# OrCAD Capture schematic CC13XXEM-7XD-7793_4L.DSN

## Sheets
1 CC13xxEM-7XD-7793_4L: size A3; title: CC13xxEM-7XD-7793_4L, main; rev: 1.0.1
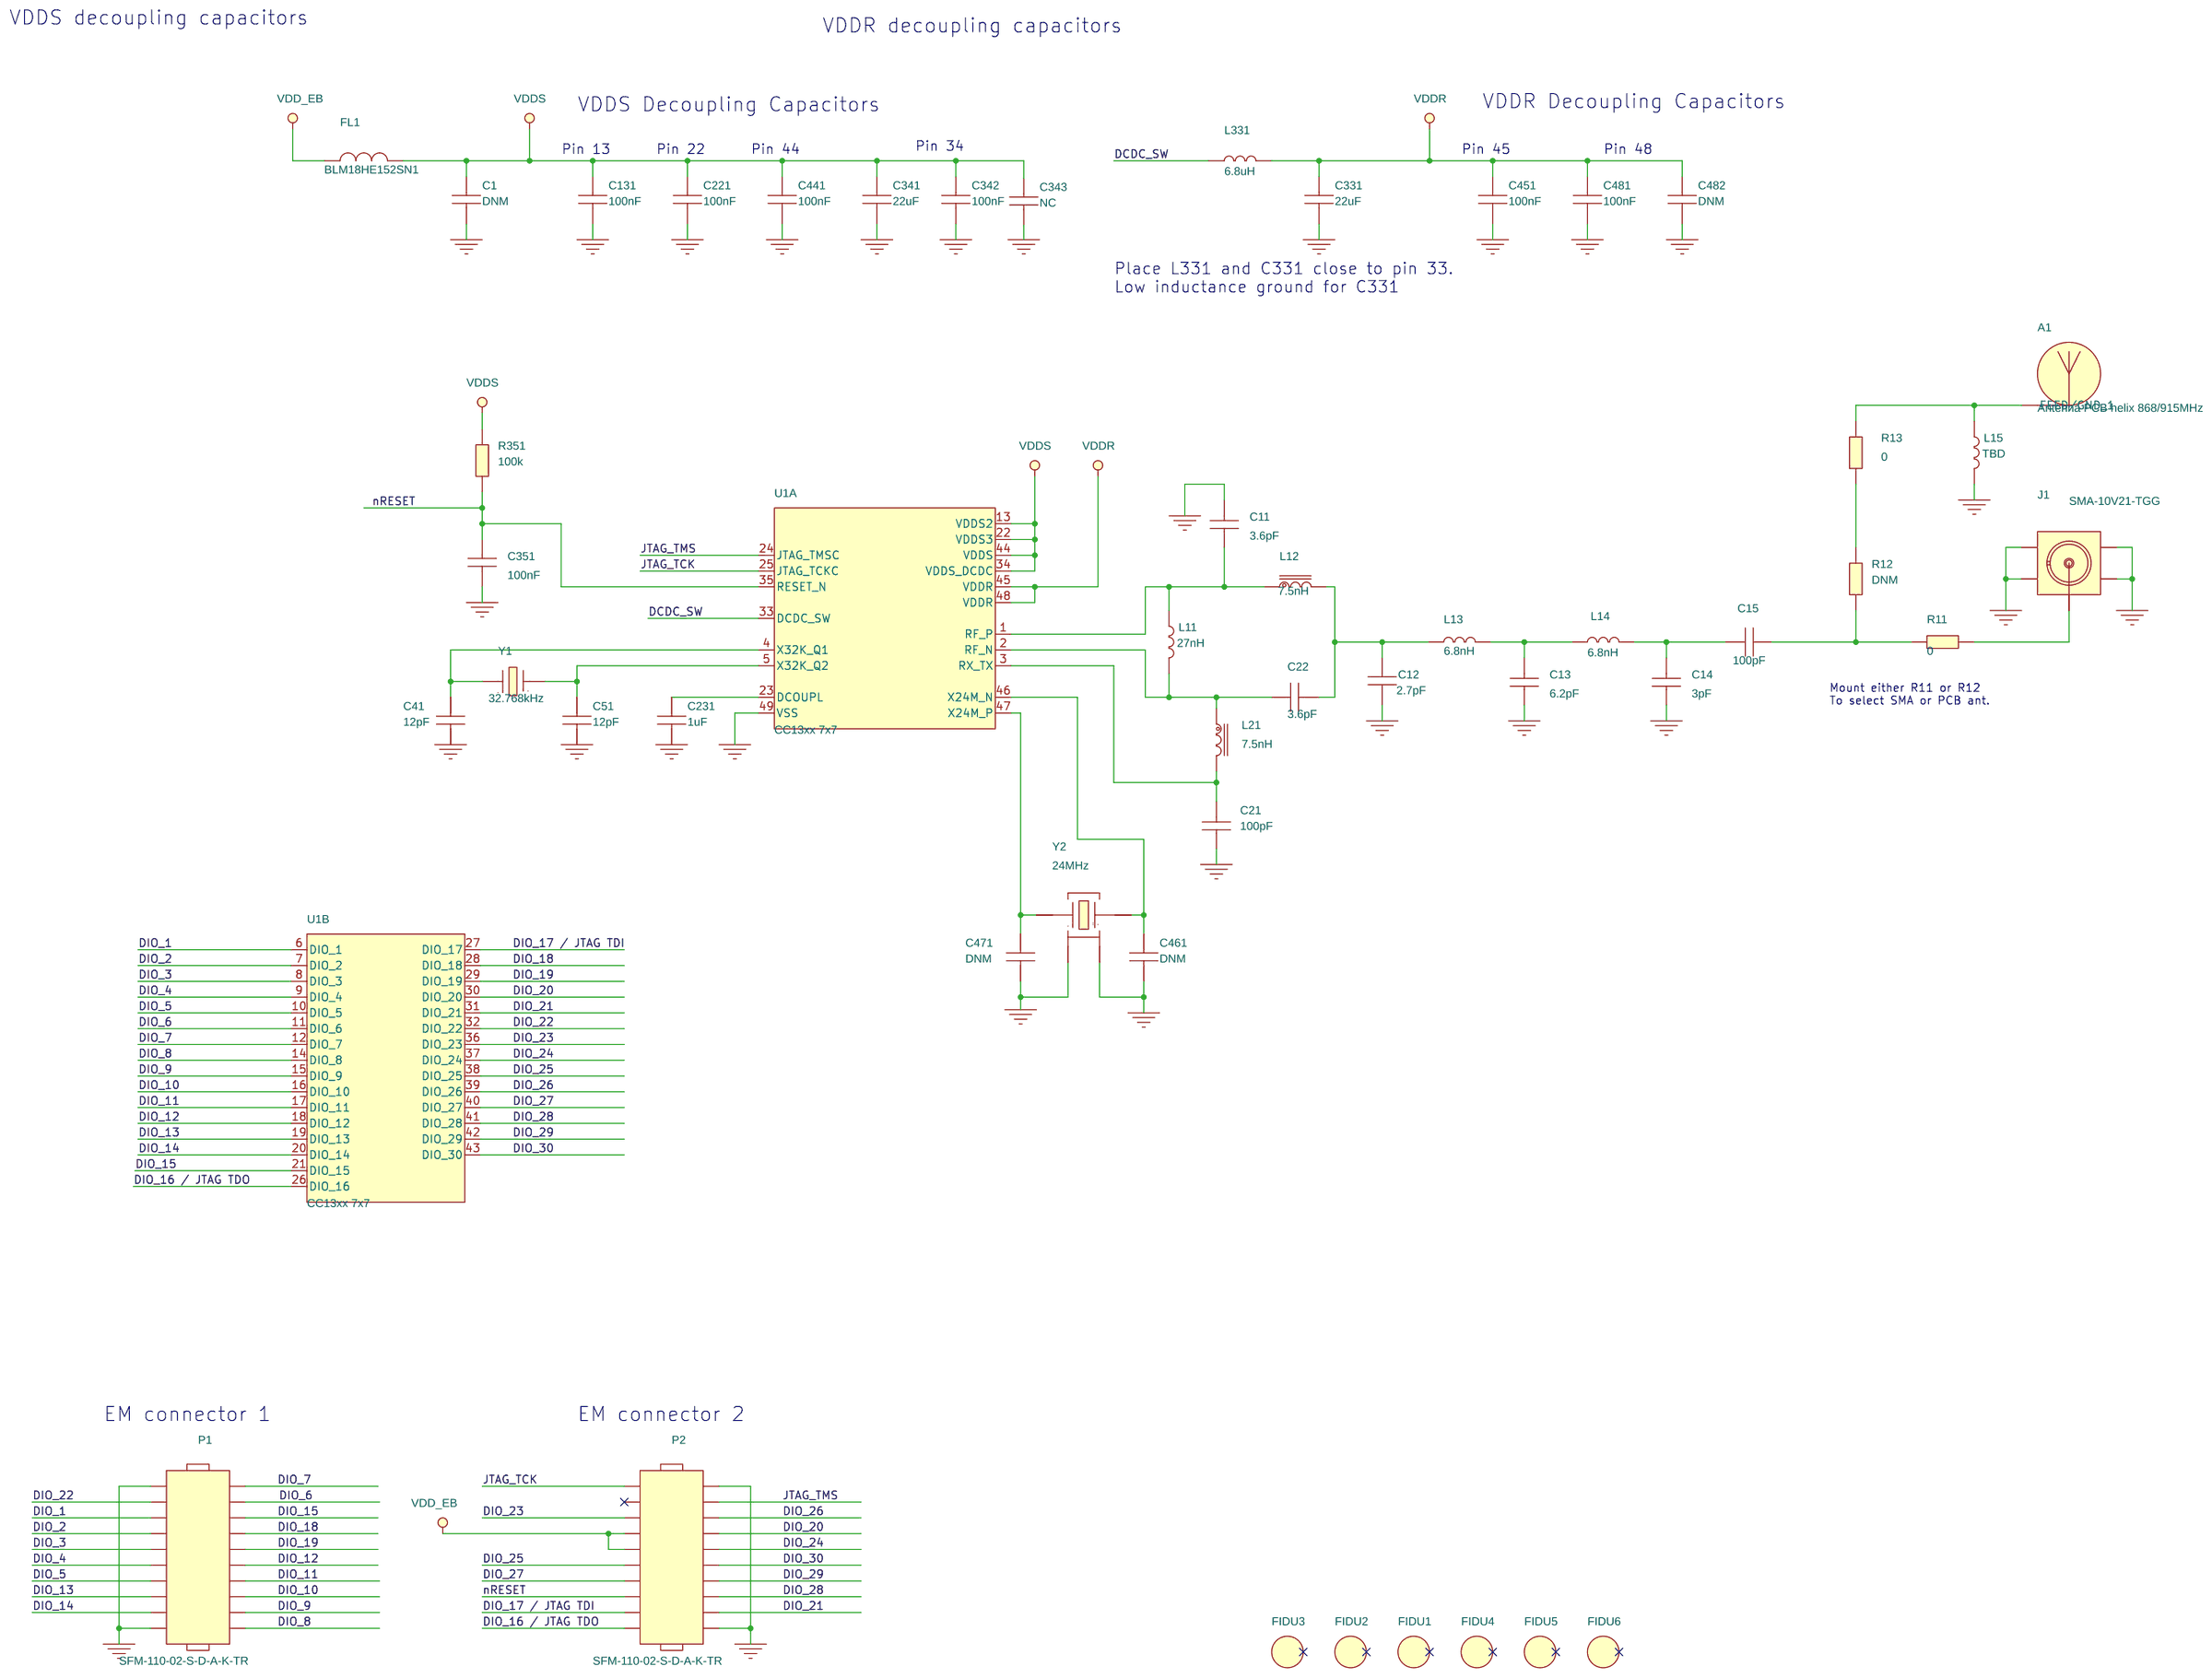
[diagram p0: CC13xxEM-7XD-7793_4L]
2 Revision: title: CC13xxEM-7XD-7793_4L, rev history
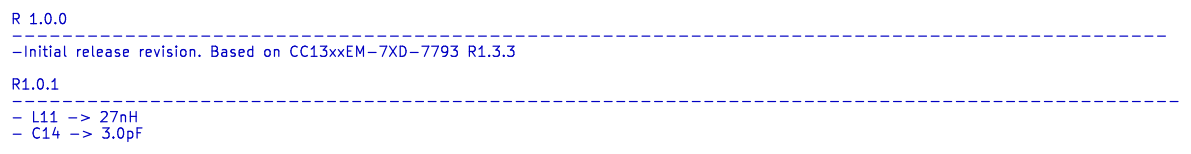
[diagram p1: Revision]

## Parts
A1  Antenna PCB helix 868/915MHz  [Antenna868_915MHz_A2N]
C1  DNM  [CAPC1608X90L]
C11  3.6pF  [CAPC1005X60L]
C12  2.7pF  [CAPC1005X60L]
C13  6.2pF  [CAPC1005X60L]
C14  3pF  [CAPC1005X60L]
C15  100pF  [CAPC1005X60L]
C21  100pF  [CAPC1005X60L]
C22  3.6pF  [CAPC1005X60L]
C41  12pF  [CAPC1005X60L]
C51  12pF  [CAPC1005X60L]
C131  100nF  [CAPC1005X60L]
C221  100nF  [CAPC1005X60L]
C231  1uF  [CAPC1005X60L]
C331  22uF  [CAPC1608X100A2L]
C341  22uF  [CAPC1608X100A2L]
C342  100nF  [CAPC1608X90L]
C343  NC  [CAPC1608X90L]
C351  100nF  [CAPC1005X60L]
C441  100nF  [CAPC1005X60L]
C451  100nF  [CAPC1005X60L]
C461  DNM  [CAPC1005X60L]
C471  DNM  [CAPC1005X60L]
C481  100nF  [CAPC1005X60L]
C482  DNM  [CAPC1005X60L]
FIDU1  FIDU_1MM  [FID100X115]
FIDU2  FIDU_1MM  [FID100X115]
FIDU3  FIDU_1MM  [FID100X115]
FIDU4  FIDU_1MM  [FID100X115]
FIDU5  FIDU_1MM  [FID100X115]
FIDU6  FIDU_1MM  [FID100X115]
FL1  BLM18HE152SN1  [FIL_BLM18HE152SN1DL]
J1  SMA-10V21-TGG  [HUSTSAN_SMA10V21TGGAN]
L11  27nH  [INDC1005X60L]
L12  7.5nH  [INDC1005X60A2L]
L13  6.8nH  [INDC1005X60L]
L14  6.8nH  [INDC1005X60L]
L15  TBD  [INDC1005X60L]
L21  7.5nH  [INDC1005X60A2L]
L331  6.8uH  [INDC2012X150L]
P1  SFM-110-02-S-D-A-K-TR  [SAMTEC_SFM11002AN]
P2  SFM-110-02-S-D-A-K-TR  [SAMTEC_SFM11002AN]
R11  0  [RESC1005X40L]
R12  DNM  [RESC1005X40L]
R13  0  [RESC1005X40L]
R351  100k  [RESC1005X40L]
U1  CC13xx 7x7  [QFNFC50P700X700X80-49CN]  (sections A,B)
Y1  32.768kHz  [XTAL_FC-135N]
Y2  24MHz  [OSCCC250X320X60-4L]

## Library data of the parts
A1 = ANTENNA: ANTENNA, NON COMPONENT, PCB HELIX 868/915MHz, NOT APPLY; AutoDoc File: http://notefied-dynamic-precision.com/DB/Apps/Desktop/Item/Object.aspx?id=87165; Budget Currency: N/A; Budget Price: N/A; Datasheet URL 1: N/A; Datasheet URL 2: www.ti.com; Definied Quality: COMMERCIAL; Esd Level: N/A; FPLIST: Antenna868_915MHz_A2N,Antenna868_915MHz_MIRROR_A2N,; Frequency: 868/915MHz; Last Time Buy: N/A; Lead Time: N/A; LifeCycle Status: ACTIVE; MPN: ANTENNA PCB HELIX 868/915MHz; MPN Status: ACTIVE; MSL: N/A; MTBF: N/A; MTBF Standard: N/A; Manufacturer: TEXAS INSTRUMENTS; Max Oper Temp: N/A; Min Oper Temp: N/A; Mounting Type: NOT APPLY; NOTE Status: PREFERRED; Old Footprint: Antenna868_915MHz_A2N,Antenna868_915MHz_MIRROR_A2N; Packing Size: 2500; Packing Type: TAPE_&_REEL; Part Number: 13-00397; Part Type: MECHANIC\ANTENNA\NON_COMPONENT; Revision: R003; RoHS Status: ROHS_COMPLIANT; WEIGHT: N/A
C1 = CAPACITOR: CAPACITOR, DO NOT MOUNT, 0603, SMD; ALT_SYMBOLS: CAPC1608X90L,CAPC1608X90M; AutoDoc File: http://notefied-dynamic-precision.com/DB/Apps/Desktop/Item/Object.aspx?id=50475; FPLIST: CAPC1608X90N,CAPC1608X90L,CAPC1608X90M; Old Footprint: CAPC1608X90N,0603; Part Number: 02-01324; Part Type: CAPACITOR\CERAMIC\0603; Revision: R003
C11 C22 = CAPACITOR: CAPACITOR, CERAMIC C0G/NP0, 3.6pF, 50V, -0.25pF/+0.25pF, -55DEGC/+125DEGC, 0402, SMD; ALT_SYMBOLS: CAPC1005X60L,CAPC1005X60M; AutoDoc File: http://notefied-dynamic-precision.com/DB/Apps/Desktop/Item/Object.aspx?id=95903; Datasheet URL 2: http://psearch.murata.com/capacitor/product/GRM1555C1H3R6CA01%23.pdf; Dielectric Type: C0G/NP0; FPLIST: CAPC1005X60N,CAPC1005X60L,CAPC1005X60M; MPN: GRM1555C1H3R6CA01D; MPN Status: ACTIVE; Manufacturer: MURATA; Max Oper Temp: +125DEGC; Max Tol: +0.25pF; Min Oper Temp: -55DEGC; Min Tol: -0.25pF; Mounting Type: SMD; NOTE Status: PREFERRED; Old Footprint: CAPC1005X60N; PCB Package: 0402; Packing Size: 10000; Packing Type: TAPE_&_REEL; Part Number: 02-06008; Part Type: CAPACITOR\CERAMIC\0402; Revision: R001; RoHS Status: ROHS_COMPLIANT; Rtd Voltage: 50V
C12 = CAPACITOR: CAPACITOR, CERAMIC C0G/NP0, 2.7pF, 50V, -0.25pF/+0.25pF, -55DEGC/+125DEGC, 0402, SMD; ALT_SYMBOLS: CAPC1005X60L,CAPC1005X60M; AutoDoc File: http://notefied-dynamic-precision.com/DB/Apps/Desktop/Item/Object.aspx?id=87809; Budget Currency: EUR; Budget Price: 0.006; Datasheet URL 1: http://search.murata.co.jp/Ceramy/image/img/w_hinm/L0005E.pdf; Datasheet URL 2: http://psearch.murata.com/capacitor/product/GRM1555C1H2R7CA01%23.pdf; Definied Quality: INDUSTRIAL; Dielectric Type: C0G/NP0; Esd Level: N/A; FPLIST: CAPC1005X60N,CAPC1005X60L,CAPC1005X60M; Last Time Buy: N/A; Lead Time: 12; MPN: GRM1555C1H2R7CA01D; MPN Status: ACTIVE; MSL: 1; MTBF: N/A; MTBF Standard: N/A; Manufacturer: MURATA; Max Oper Temp: +125DEGC; Max Tol: +0.25pF; Min Oper Temp: -55DEGC; Min Tol: -0.25pF; Mounting Type: SMD; NOTE Status: PREFERRED; Old Footprint: CAPC1005X60N; PCB Package: 0402; Packing Size: 10000; Packing Type: TAPE_&_REEL; Part Number: 02-04679; Part Type: CAPACITOR\CERAMIC\0402; Revision: R001; RoHS Status: ROHS_COMPLIANT; Rtd Voltage: 50V; WEIGHT: 0.0016g
C13 = CAPACITOR: CAPACITOR, CERAMIC C0G/NP0, 6.2pF, 50V, -0.25pF/+0.25pF, -55DEGC/+125DEGC, 0402, SMD; ALT_SYMBOLS: CAPC1005X60L,CAPC1005X60M; AutoDoc File: http://notefied-dynamic-precision.com/DB/Apps/Desktop/Item/Object.aspx?id=87255; Budget Currency: EUR; Budget Price: 0.006; Datasheet URL 1: http://search.murata.co.jp/Ceramy/image/img/w_hinm/L0005E.pdf; Datasheet URL 2: http://psearch.murata.com/capacitor/product/GRM1555C1H6R2CA01%23.pdf; Definied Quality: INDUSTRIAL; Dielectric Type: C0G/NP0; Esd Level: N/A; FPLIST: CAPC1005X60N,CAPC1005X60L,CAPC1005X60M; Last Time Buy: N/A; Lead Time: 10; MPN: GRM1555C1H6R2CA01D; MPN Status: ACTIVE; MSL: 1; MTBF: N/A; MTBF Standard: N/A; Manufacturer: MURATA; Max Oper Temp: +125DEGC; Max Tol: +0.25pF; Min Oper Temp: -55DEGC; Min Tol: -0.25pF; Mounting Type: SMD; NOTE Status: PREFERRED; Old Footprint: CAPC1005X60N; PCB Package: 0402; Packing Size: 10000; Packing Type: TAPE_&_REEL; Part Number: 02-04608; Part Type: CAPACITOR\CERAMIC\0402; Revision: R001; RoHS Status: ROHS_COMPLIANT; Rtd Voltage: 50V; WEIGHT: 0.0016g
C14 = CAPACITOR: CAPACITOR, CERAMIC C0G/NP0, 3pF, 50V, -0.25pF/+0.25pF, -55DEGC/+125DEGC, 0402, SMD; ALT_SYMBOLS: CAPC1005X60L,CAPC1005X60M; AutoDoc File: http://notefied-dynamic-precision.com/DB/Apps/Desktop/Item/Object.aspx?id=87252; Budget Currency: EUR; Budget Price: 0.006; Datasheet URL 1: http://search.murata.co.jp/Ceramy/image/img/w_hinm/L0005E.pdf; Datasheet URL 2: http://psearch.murata.com/capacitor/product/GRM1555C1H3R0CA01%23.pdf; Definied Quality: INDUSTRIAL; Dielectric Type: C0G/NP0; Esd Level: N/A; FPLIST: CAPC1005X60N,CAPC1005X60L,CAPC1005X60M; Last Time Buy: N/A; Lead Time: 16; LifeCycle Status: ACTIVE; MPN: GRM1555C1H3R0CA01D; MPN Status: ACTIVE; MSL: 1; MTBF: N/A; MTBF Standard: N/A; Manufacturer: MURATA; Max Oper Temp: +125DEGC; Max Tol: +0.25pF; Min Oper Temp: -55DEGC; Min Tol: -0.25pF; Mounting Type: SMD; NOTE Status: PREFERRED; Old Footprint: CAPC1005X60N; PCB Package: 0402; Packing Size: 10000; Packing Type: TAPE_&_REEL; Part Number: 02-04606; Part Type: CAPACITOR\CERAMIC\0402; Revision: R001; RoHS Status: ROHS_COMPLIANT; Rtd Voltage: 50V; WEIGHT: 0.0016g
C15 C21 = CAPACITOR: CAPACITOR, CERAMIC C0G/NP0, 100pF, 50V, -5%/+5%, -55DEGC/+125DEGC, 0402, SMD; ALT_SYMBOLS: CAPC1005X60L,CAPC1005X60M; AutoDoc File: http://notefied-dynamic-precision.com/DB/Apps/Desktop/Item/Object.aspx?id=86072; Budget Currency: EUR; Budget Price: 0.006; Datasheet URL 1: http://search.murata.co.jp/Ceramy/image/img/w_hinm/L0005E.pdf; Datasheet URL 2: http://psearch.murata.com/capacitor/product/GRM1555C1H101JA01%23.pdf; Definied Quality: INDUSTRIAL; Dielectric Type: C0G/NP0; Esd Level: N/A; FPLIST: CAPC1005X60N,CAPC1005X60L,CAPC1005X60M; Last Time Buy: N/A; Lead Time: 12; MPN: GRM1555C1H101JA01D; MPN Status: ACTIVE; MSL: 1; MTBF: N/A; MTBF Standard: N/A; Manufacturer: MURATA; Max Oper Temp: +125DEGC; Max TC: +30PPM/DEGC; Max Tol: +5%; Min Oper Temp: -55DEGC; Min TC: -30PPM/DEGC; Min Tol: -5%; Mounting Type: SMD; NOTE Status: PREFERRED; Old Footprint: CAPC1005X60N; PCB Package: 0402; Packing Size: 10000; Packing Type: TAPE_&_REEL; Part Number: 02-04365; Part Type: CAPACITOR\CERAMIC\0402; Revision: R002; RoHS Status: ROHS_COMPLIANT; Rtd Voltage: 50V; WEIGHT: 0.0016g
C41 C51 = CAPACITOR: CAPACITOR, CERAMIC C0G/NP0, 12pF, 50V, -5%/+5%, -55DEGC/+125DEGC, 0402, SMD; ALT_SYMBOLS: CAPC1005X60L,CAPC1005X60M; AutoDoc File: http://notefied-dynamic-precision.com/DB/Apps/Desktop/Item/Object.aspx?id=84867; Budget Currency: EUR; Budget Price: 0.006; Datasheet URL 1: http://search.murata.co.jp/Ceramy/image/img/w_hinm/L0005E.pdf; Datasheet URL 2: http://psearch.murata.com/capacitor/product/GRM1555C1H120JA01%23.pdf; Definied Quality: INDUSTRIAL; Dielectric Type: C0G/NP0; Esd Level: N/A; FPLIST: CAPC1005X60N,CAPC1005X60L,CAPC1005X60M; Last Time Buy: N/A; Lead Time: 12; MPN: GRM1555C1H120JA01D; MPN Status: ACTIVE; MSL: 1; MTBF: N/A; MTBF Standard: N/A; Manufacturer: MURATA; Max Oper Temp: +125DEGC; Max TC: +30PPM/DEGC; Max Tol: +5%; Min Oper Temp: -55DEGC; Min TC: -30PPM/DEGC; Min Tol: -5%; Mounting Type: SMD; NOTE Status: PREFERRED; Old Footprint: CAPC1005X60N; PCB Package: 0402; Packing Size: 10000; Packing Type: TAPE_&_REEL; Part Number: 02-04168; Part Type: CAPACITOR\CERAMIC\0402; Revision: R000; RoHS Status: ROHS_COMPLIANT; Rtd Voltage: 50V; WEIGHT: 0.0016g
C131 C221 C351 C441 C451 C481 = CAPACITOR: CAPACITOR, CERAMIC X7R, 100nF, 6.3V, -10%/+10%, -55DEGC/+125DEGC, 0402, SMD; ALT_SYMBOLS: CAPC1005X60L,CAPC1005X60M; AutoDoc File: http://notefied-dynamic-precision.com/DB/Apps/Desktop/Item/Object.aspx?id=73748; Budget Currency: EUR; Budget Price: 0.003; Datasheet URL 1: http://search.murata.co.jp/Ceramy/image/img/A01X/G101/ENG/GRM155R70J104KA01-01.pdf; Datasheet URL 2: http://search.murata.co.jp/Ceramy/image/img/A01X/G101/ENG/GRM155R70J104KA01-01.pdf; Dielectric Type: X7R; FPLIST: CAPC1005X60N,CAPC1005X60L,CAPC1005X60M; Lead Time: 10; LifeCycle Status: ACTIVE; MPN: GRM155R70J104KA01D; MPN Status: ACTIVE; Manufacturer: MURATA; Max Oper Temp: +125DEGC; Max Tol: +10%; Min Oper Temp: -55DEGC; Min Tol: -10%; Mounting Type: SMD; NOTE Status: PREFERRED; Old Footprint: CAPC1005X60N,0402; PCB Package: 0402; Packing Size: 10000; Packing Type: TAPE_&_REEL; Part Number: 02-02323; Part Type: CAPACITOR\CERAMIC\0402; Revision: R000; RoHS Status: ROHS_COMPLIANT; Rtd Voltage: 6.3V; WEIGHT: 0.0016g
C231 = CAPACITOR: CAPACITOR, CERAMIC X5R, 1uF, 10V, -10%/+10%, -55DEGC/+85DEGC, 0402, SMD; ALT_SYMBOLS: CAPC1005X60L,CAPC1005X60M; AutoDoc File: http://notefied-dynamic-precision.com/DB/Apps/Desktop/Item/Object.aspx?id=74236; Budget Currency: EUR; Budget Price: 0.015; Datasheet URL 1: http://search.murata.co.jp/Ceramy/image/img/w_hinm/L0005E.pdf; Datasheet URL 2: http://psearch.murata.com/capacitor/product/GRM155R61A105KE15%23.pdf; Definied Quality: INDUSTRIAL; Dielectric Type: X5R; Esd Level: N/A; FPLIST: CAPC1005X60N,CAPC1005X60L,CAPC1005X60M; Last Time Buy: N/A; Lead Time: 14; MPN: GRM155R61A105KE15D; MPN Status: ACTIVE; MSL: 1; MTBF: N/A; MTBF Standard: N/A; Manufacturer: MURATA; Max Oper Temp: +85DEGC; Max Tol: +10%; Min Oper Temp: -55DEGC; Min Tol: -10%; Mounting Type: SMD; NOTE Status: PREFERRED; Old Footprint: CAPC1005X60N,0402; PCB Package: 0402; Packing Size: 10000; Packing Type: TAPE_&_REEL; Part Number: 02-02381; Part Type: CAPACITOR\CERAMIC\0402; Revision: R002; RoHS Status: ROHS_COMPLIANT; Rtd Voltage: 10V; WEIGHT: 0.0016g
C331 C341 = CAPACITOR: CAPACITOR, CERAMIC, X5R, 22uF, 6.3V, -20%/+20%, -55DEGC/+85DEGC, 0603, SMD; ALT_SYMBOLS: CAPC1608X100A2L,CAPC1608X100A2M; AutoDoc File: http://notefied-dynamic-precision.com/DB/Apps/Desktop/Item/Object.aspx?id=104385; Budget Currency: USD; Budget Price: 0.045; Datasheet URL 1: N/A; Datasheet URL 2: http://psearch.en.murata.com/capacitor/product/GRM188R60J226MEA0%23.pdf; Definied Quality: INDUSTRIAL; Dielectric Type: X5R; Esd Level: N/A; FPLIST: CAPC1608X100A2N,CAPC1608X100A2L,CAPC1608X100A2M; Last Time Buy: N/A; Lead Time: 26; LifeCycle Status: ACTIVE; MPN: GRM188R60J226MEA0D; MPN Status: ACTIVE; Manufacturer: MURATA; Max Oper Temp: +85DEGC; Max Tol: +20%; Min Oper Temp: -55DEGC; Min Tol: -20%; Mounting Type: SMD; NOTE Status: PREFERRED; Old Footprint: CAPC1608X100A2N; PCB Package: 0603; Packing Size: 4000; Packing Type: TAPE_&_REEL; Part Number: 02-07053; Part Type: CAPACITOR\CERAMIC\0603; Revision: R001; RoHS Status: ROHS_COMPLIANT; Rtd Voltage: 6.3V; WEIGHT: 0.0091g
C342 = CAPACITOR: CAPACITOR, CERAMIC X7R, 100nF, 25V, -10%/+10%, -55DEGC/+125DEGC, 0603, SMD; ALT_SYMBOLS: CAPC1608X90L,CAPC1608X90M; AutoDoc File: http://notefied-dynamic-precision.com/DB/Apps/Desktop/Item/Object.aspx?id=72070; Budget Currency: EUR; Budget Price: 0.006; Cage Code: C0151; Datasheet URL 1: http://search.murata.co.jp/Ceramy/image/img/w_hinm/L0005E.pdf; Datasheet URL 2: http://psearch.murata.com/capacitor/product/GRM188R71E104KA01%23.pdf; Definied Quality: INDUSTRIAL; Dielectric Type: X7R; Esd Level: N/A; FPLIST: CAPC1608X90N,CAPC1608X90L,CAPC1608X90M; Last Time Buy: N/A; Lead Time: 10; MPN: GRM188R71E104KA01D; MPN Status: NRND; MSL: 1; MTBF: N/A; MTBF Standard: N/A; Manufacturer: MURATA; Max Oper Temp: +125DEGC; Max Tol: +10%; Min Oper Temp: -55DEGC; Min Tol: -10%; Mounting Type: SMD; NOTE Status: PREFERRED; Old Footprint: CAPC1608X90N,0603; PCB Package: 0603; Packing Size: 4000; Packing Type: TAPE_&_REEL; Part Number: 02-01992; Part Type: CAPACITOR\CERAMIC\0603; Revision: R001; RoHS Status: ROHS_COMPLIANT; Rtd Voltage: 25V; WEIGHT: 0.0063g
C343 = CAPACITOR: CAPACITOR, CERAMIC, N/A VALUE, -55DEGC/+125DEGC, 0603, SMD; ALT_SYMBOLS: CAPC1608X90L,CAPC1608X90M; AutoDoc File: http://notefied-dynamic-precision.com/DB/Apps/Desktop/Item/Object.aspx?id=50386; Budget Currency: USD; Budget Price: 0.00262; Datasheet URL 1: N/A; Datasheet URL 2: N/A; Definied Quality: INDUSTRIAL; Esd Level: N/A; FPLIST: CAPC1608X90N,CAPC1608X90L,CAPC1608X90M; Last Time Buy: N/A; Lead Time: N/A; MPN: CAPACITOR_0603_N/A_M; MPN Status: ACTIVE; MSL: N/A; MTBF: N/A; MTBF Standard: N/A; Manufacturer: MANUFACTURER SELECTION; Max Oper Temp: +125DEGC; Min Oper Temp: -55DEGC; Mounting Type: SMD; NOTE Status: PREFERRED; Old Footprint: CAPC1608X90N,0603; PCB Package: 0603; Packing Size: 5000; Packing Type: TAPE_&_REEL; Part Number: 02-01235; Part Type: CAPACITOR\CERAMIC\0603; Revision: R001; RoHS Status: ROHS_COMPLIANT; WEIGHT: 0.002g
C461 C471 C482 = CAPACITOR: CAPACITOR, CERAMIC, N/A VALUE, -55DEGC/+125DEGC, 0402, SMD; ALT_SYMBOLS: CAPC1005X60L,CAPC1005X60M; AutoDoc File: http://notefied-dynamic-precision.com/DB/Apps/Desktop/Item/Object.aspx?id=84862; Budget Currency: USD; Budget Price: 0.00589; FPLIST: CAPC1005X60N,CAPC1005X60L,CAPC1005X60M; MPN: CAPACITOR_0402_DNM_N/A_M; MPN Status: ACTIVE; Manufacturer: Manufacturer selection; Max Oper Temp: +125DEGC; Min Oper Temp: -55DEGC; Mounting Type: SMD; NOTE Status: PREFERRED; Old Footprint: CAPC1005X60N; PCB Package: 0402; Packing Size: 10000; Packing Type: TAPE_&_REEL; Part Number: 02-04164; Part Type: CAPACITOR\CERAMIC\0402; Revision: R000; RoHS Status: PART NOT KNOWN
FIDU1-FIDU6 = FIDMARK: FIDUCIAL MARK, ROUND 1MM; AutoDoc File: http://notefied-dynamic-precision.com/DB/Apps/Desktop/Item/Object.aspx?id=74548; Part Number: 19-00111; Part Type: NON_COMPONENT\FIDUCIAL; Revision: R001
FL1 = FILTER_2PIN: FILTER, EMI, 1500@100MHz, -55DEGC/+125DEGC, 0603, SMD; ALT_SYMBOLS: FIL_BLM18HE152SN1DL,FIL_BLM18HE152SN1DM; AutoDoc File: http://notefied-dynamic-precision.com/DB/Apps/Desktop/Item/Object.aspx?id=85575; Budget Currency: EUR; Budget Price: 0.085; Datasheet URL 1: http://search.murata.co.jp/Ceramy/image/img/PDF/ENG/L0110S0101BLM18H.pdf; Datasheet URL 2: http://search.murata.co.jp/Ceramy/image/img/PDF/ENG/L0110S0101BLM18H.pdf; FPLIST: FIL_BLM18HE152SN1DN,FIL_BLM18HE152SN1DL,FIL_BLM18HE152SN1DM; Impedance: 1500@100MHz; Lead Time: 26; MPN: BLM18HE152SN1D; MPN Status: ACTIVE; Manufacturer: MURATA; Max Oper Temp: +125DEGC; Max Tol: +25%; Min Oper Temp: -55DEGC; Min Tol: -25%; Mounting Type: SMD; NOTE Status: PREFERRED; Old Footprint: FIL_BLM18HE152SN1DN; PCB Package: 0603; Packing Size: 4000; Packing Type: TAPE_&_REEL; Part Number: 04-00470; Part Type: FILTER\EMI\0603; Revision: R001; RoHS Status: ROHS_COMPLIANT; Rtd Current: 0.5A; WEIGHT: 0.006g
J1 = CONN_COAX_1+4: CONNECTOR, COAX RF, STRAIGHT, FEMALE, 1 PIN, SMD; ALT_SYMBOLS: HUSTSAN_SMA10V21TGGL,HUSTSAN_SMA10V21TGGM; AutoDoc File: http://notefied-dynamic-precision.com/DB/Apps/Desktop/Item/Object.aspx?id=84956; Budget Currency: USD; Budget Price: 1.21; Datasheet URL 1: http://www.hustsan.com.tw/uploaddir/product/SMA-10V21.pdf; Datasheet URL 2: http://www.hustsan.com.tw/uploaddir/product/SMA-10V21.pdf; FPLIST: HUSTSAN_SMA10V21TGGAN,HUSTSAN_SMA10V21TGGN; Lead Time: 5; MPN Status: ACTIVE; MSL: N/A; Manufacturer: HUS-TSAN; Mounting Type: SMD; NOTE Status: PREFERRED; No Of Pos: 1; Old Footprint: HUSTSAN_SMA10V21TGGAN,HUSTSAN_SMA10V21TGGN; Packing Size: 350; Packing Type: TAPE_&_REEL; Part Number: 06-02188; Part Type: CONNECTOR\COAX; Revision: R003; RoHS Status: N/A; WEIGHT: N/A
L11 = INDUCTOR: INDUCTOR, STANDARD, CHIP, 27nH, -5%/+5%, 0.3A, -55DEGC/+125DEGC, 0402, SMD; ALT_SYMBOLS: INDC1005X60M,INDC1005X60L; AutoDoc File: http://notefied-dynamic-precision.com/DB/Apps/Desktop/Item/Object.aspx?id=85867; Budget Currency: EUR; Budget Price: 0.03; Datasheet URL 1: N/A; Datasheet URL 2: http://psearch.murata.com/inductor/product/LQG15HS27NJ02%23.pdf; Definied Quality: INDUSTRIAL; Esd Level: N/A; FPLIST: INDC1005X60N,INDC1005X60M,INDC1005X60L; Frequency: 1700MHz; Last Time Buy: N/A; Lead Time: 9; LifeCycle Status: ACTIVE; MPN: LQG15HS27NJ02D; MPN Status: ACTIVE; MSL: N/A; MTBF: N/A; MTBF Standard: N/A; Manufacturer: MURATA; Max Oper Temp: +125DEGC; Max Tol: +5%; Min Oper Temp: -55DEGC; Min Tol: -5%; Mounting Type: SMD; NOTE Status: PREFERRED; Old Footprint: INDC1005X60N; PCB Package: 0402; Packing Size: 10000; Packing Type: TAPE_&_REEL; Part Number: 03-06536; Part Type: INDUCTOR\CHIP\0402; Resistance: 0.46; Revision: R001; RoHS Status: ROHS_COMPLIANT; Rtd Current: 0.3A; WEIGHT: 0.001g
L12 L21 = IND_HOR: INDUCTOR, CHIP, 7.5nH, -5%/+5%, IR:0.55A, -55DEGC/+125DEGC, 0402, SMD; ALT_SYMBOLS: INDC1005X60A2L,INDC1005X60A2M; AutoDoc File: http://notefied-dynamic-precision.com/DB/Apps/Desktop/Item/Object.aspx?id=101601; Budget Currency: EUR; Budget Price: 0.024; Datasheet URL 1: N/A; Datasheet URL 2: http://psearch.en.murata.com/inductor/product/LQG15HS7N5J02%23.pdf; Definied Quality: INDUSTRIAL; FPLIST: INDC1005X60A2N,INDC1005X60A2L,INDC1005X60A2M; Frequency: 4.2GHz; Last Time Buy: N/A; Lead Time: 10; LifeCycle Status: NRND; MPN: LQG15HS7N5J02D; MPN Status: NRND; MSL: N/A; Manufacturer: MURATA; Max Oper Temp: +125DEGC; Max Tol: +5%; Min Oper Temp: -55DEGC; Min Tol: -5%; Mounting Type: SMD; NOTE Status: NOT_PREFERRED; Old Footprint: INDC1005X60A2N; PCB Package: 0402; Packing Size: 10000; Packing Type: TAPE_&_REEL; Part Number: 03-07022; Part Type: INDUCTOR\CHIP\0402; Resistance: 0.24; Revision: R001; RoHS Status: ROHS_COMPLIANT; Rtd Current: 0.55A; WEIGHT: 0.001g
L13 L14 = INDUCTOR: INDUCTOR, CHIP, 6.8nH, -5%/+5%, 0.3A, -55DEGC/+125DEGC, 0402, SMD; ALT_SYMBOLS: INDC1005X60L,INDC1005X60M; AutoDoc File: http://notefied-dynamic-precision.com/DB/Apps/Desktop/Item/Object.aspx?id=87737; Budget Currency: EUR; Budget Price: 0.024; Datasheet URL 1: N/A; Datasheet URL 2: http://psearch.murata.com/inductor/product/LQG15HS6N8J02%23.pdf; Definied Quality: INDUSTRIAL; Esd Level: N/A; FPLIST: INDC1005X60N,INDC1005X60L,INDC1005X60M; Frequency: 4.5GHz; Last Time Buy: N/A; Lead Time: 12; LifeCycle Status: ACTIVE; MPN: LQG15HS6N8J02D; MPN Status: ACTIVE; MSL: N/A; MTBF: N/A; MTBF Standard: N/A; Manufacturer: MURATA; Max Oper Temp: +125DEGC; Max Tol: +5%; Min Oper Temp: -55DEGC; Min Tol: -5%; Mounting Type: SMD; NOTE Status: PREFERRED; Old Footprint: INDC1005X60N; PCB Package: 0402; Packing Size: 10000; Packing Type: TAPE_&_REEL; Part Number: 03-06633; Part Type: INDUCTOR\CHIP\0402; Resistance: 0.24; Revision: R001; RoHS Status: ROHS_COMPLIANT; Rtd Current: 0.3A; WEIGHT: 0.001g
L15 = INDUCTOR: INDUCTOR, TO BE DECIDED, 0402, SMD; ALT_SYMBOLS: INDC1005X60M,INDC1005X60L; AutoDoc File: http://notefied-dynamic-precision.com/DB/Apps/Desktop/Item/Object.aspx?id=45714; Budget Currency: N/A; Budget Price: N/A; Datasheet URL 1: N/A; Datasheet URL 2: N/A; Definied Quality: COMMERCIAL; Esd Level: N/A; FPLIST: INDC1005X60N,INDC1005X60M,INDC1005X60L; Last Time Buy: N/A; Lead Time: N/A; LifeCycle Status: ACTIVE; MPN: IND_TBD_0402; MPN Status: ACTIVE; MSL: N/A; MTBF: N/A; MTBF Standard: N/A; Manufacturer: MANUFACTURER SELECTION; Mounting Type: SMD; NOTE Status: PREFERRED; Old Footprint: 0402; Packing Size: N/A; Packing Type: N/A; Part Number: 03-01022; Part Type: INDUCTOR\CHIP\0402; Revision: R002; RoHS Status: ROHS_COMPLIANT; WEIGHT: N/A
L331 = INDUCTOR: INDUCTOR, CHIP, FERRITE CORE, 6.8uH, -20%/+20%, IR:1.1A, -55DEGC/+125DEGC, 0805, SMD; ALT_SYMBOLS: INDC2012X150L,INDC2012X150M; AutoDoc File: http://notefied-dynamic-precision.com/DB/Apps/Desktop/Item/Object.aspx?id=102853; Datasheet URL 1: N/A; Datasheet URL 2: http://product.tdk.com/inductor/ind/detailed_information.php?lang=en&ref=us&part_no=MLZ2012N6R8LT000; FPLIST: INDC2012X150N,INDC2012X150L,INDC2012X150M; MPN: MLZ2012N6R8LT000; MPN Status: ACTIVE; Manufacturer: TDK; Max Oper Temp: +125DEGC; Max Tol: +20%; Min Oper Temp: -55DEGC; Min Tol: -20%; Mounting Type: SMD; NOTE Status: PREFERRED; Old Footprint: INDC2012X150N; PCB Package: 0805; Packing Size: 4000; Packing Type: TAPE_&_REEL; Part Number: 03-07266; Part Type: INDUCTOR\CHIP\0805; Resistance: 0.25; Revision: R001; RoHS Status: ROHS_COMPLIANT; Rtd Current: 1.1A; WEIGHT: 0.01g
P1 P2 = CONN_HEADER_2X10_P_S: CONNECTOR, HEADER, FEMALE, STRAIGHT, 2 ROWS, 20 PINS, PITCH 1.27mm, SMD; Alt IPC Footprints: SAMTEC_SFM11002AL,SAMTEC_SFM11002AM; AutoDoc File: https://notefied-dynamic-precision.com/NotefiedWebServices/AutoDocs.aspx?itemid=85603; Datasheet URL 1: http://www.samtec.com/ProductInformation/TechnicalSpecifications/CatalogPages.aspx?series=SFM; Datasheet URL 2: http://www.samtec.com/documents/webfiles/cpdf/SFM-1XX-XX-XX-S-XX-MKT1.pdf; MPN: SFM-110-02-SM-D-A-K-TR; MPN Status: ACTIVE; Manufacturer: SAMTEC; Max Oper Temp: +125DEGC; Min Oper Temp: -55DEGC; Mounting Type: SMD; NOTE Status: PREFERRED; No Of Pos: 20; No Of Rows: 2; Packing Size: 125; Packing Type: TAPE_&_REEL; Part Number: 06-02251; Part Type: CONNECTOR\HEADER; Pitch: 1.27mm; Revision: R001; RoHS Status: ROHS_COMPLIANT
R11 R13 = RESISTOR: RESISTOR, THICK FILM, 0, -5%/+5%, 0.063W, 50V, -55DEGC/+155DEGC, 0402, SMD; ALT_SYMBOLS: RESC1005X40L,RESC1005X40M; AutoDoc File: http://notefied-dynamic-precision.com/DB/Apps/Desktop/Item/Object.aspx?id=75642; Budget Currency: USD; Budget Price: 0.00244; Datasheet URL 1: N/A; Datasheet URL 2: N/A; Definied Quality: INDUSTRIAL; Esd Level: N/A; FPLIST: RESC1005X40N,RESC1005X40L,RESC1005X40M; Last Time Buy: N/A; Lead Time: N/A; LifeCycle Status: ACTIVE; MPN: RESISTOR_0402_0_+/-5%_50V_0.063W_M_+/-200PPM; MPN Status: ACTIVE; MSL: N/A; MTBF: N/A; MTBF Standard: N/A; Manufacturer: MANUFACTURER SELECTION; Max Oper Temp: +155DEGC; Max TC: +200PPM/DEGC; Max Tol: +5%; Min Oper Temp: -55DEGC; Min TC: -200PPM/DEGC; Min Tol: -5%; Mounting Type: SMD; NOTE Status: PREFERRED; Old Footprint: RESC1005X40N; PCB Package: 0402; Packing Size: 10000; Packing Type: TAPE_&_REEL; Part Number: 01-11587; Part Type: RESISTOR\0402; Resistor Type: THICK FILM; Revision: R001; RoHS Status: ROHS_COMPLIANT; Rtd Power: 0.063W; Rtd Voltage: 50V; WEIGHT: N/A
R12 = RESISTOR: RESISTOR, DO NOT MOUNT, 0402, SMD; ALT_SYMBOLS: RESC1005X40L,RESC1005X40M; AutoDoc File: http://notefied-dynamic-precision.com/DB/Apps/Desktop/Item/Object.aspx?id=48356; Budget Currency: N/A; Budget Price: N/A; Datasheet URL 1: N/A; Datasheet URL 2: N/A; Esd Level: N/A; FPLIST: RESC1005X40N,RESC1005X40L,RESC1005X40M; Last Time Buy: N/A; Lead Time: N/A; MPN Status: ACTIVE; MSL: N/A; MTBF: N/A; MTBF Standard: N/A; Manufacturer: DO NOT MOUNT; Max Oper Temp: N/A; Min Oper Temp: N/A; Mounting Type: SMD; NOTE Status: PREFERRED; Old Footprint: RESC1005X40N,0402; PCB Package: 0402; Packing Size: N/A; Part Number: 01-02472; Part Type: RESISTOR\0402; Revision: R002; RoHS Status: PART NOT KNOWN; WEIGHT: N/A
R351 = RESISTOR: RESISTOR, THICK FILM, 100k, -1%/+1%, 0.063W, 50V, -55DEGC/+155DEGC, 0402, SMD; ALT_SYMBOLS: RESC1005X40L,RESC1005X40M; AutoDoc File: http://notefied-dynamic-precision.com/DB/Apps/Desktop/Item/Object.aspx?id=76892; Budget Currency: USD; Budget Price: 0.00244; Datasheet URL 1: N/A; Datasheet URL 2: N/A; Definied Quality: INDUSTRIAL; Esd Level: N/A; FPLIST: RESC1005X40N,RESC1005X40L,RESC1005X40M; Last Time Buy: N/A; Lead Time: N/A; LifeCycle Status: ACTIVE; MPN: RESISTOR_0402_100k_+/-1%_50V_0.063W_M_+/-100PPM; MPN Status: ACTIVE; MSL: N/A; MTBF: N/A; MTBF Standard: N/A; Manufacturer: MANUFACTURER SELECTION; Max Oper Temp: +155DEGC; Max TC: +100PPM/DEGC; Max Tol: +1%; Min Oper Temp: -55DEGC; Min TC: -100PPM/DEGC; Min Tol: -1%; Mounting Type: SMD; NOTE Status: PREFERRED; Old Footprint: RESC1005X40N; PCB Package: 0402; Packing Size: 10000; Packing Type: TAPE_&_REEL; Part Number: 01-12837; Part Type: RESISTOR\0402\PRECISION; Resistor Type: THICK FILM; Revision: R002; RoHS Status: ROHS_COMPLIANT; Rtd Power: 0.063W; Rtd Voltage: 50V; WEIGHT: N/A
U1 = IC_RF_CC13XX_7X7_QFN48_V2: IC, DIGITAL, CUSTOM, CC13xx 7x7, QFN48, SMD; ALT_SYMBOLS: QFNFC50P700X700X80-49CL,QFNFC50P700X700X80-49CM; AutoDoc File: http://notefied-dynamic-precision.com/DB/Apps/Desktop/Item/Object.aspx?id=90625; Budget Currency: N/A; Budget Price: N/A; Datasheet URL 1: N/A; Datasheet URL 2: www.ti.com; Definied Quality: COMMERCIAL; Esd Level: N/A; FPLIST: QFNFC50P700X700X80-49CN,QFNFC50P700X700X80-49CL,QFNFC50P700X700X80-49CM; Last Time Buy: N/A; Lead Time: N/A; MPN Status: ACTIVE; MSL: N/A; MTBF: N/A; MTBF Standard: N/A; Manufacturer: TEXAS INSTRUMENTS; Max Oper Temp: N/A; Min Oper Temp: N/A; Mounting Type: SMD; NOTE Status: PREFERRED; PCB Package: QFN48; Packing Size: N/A; Packing Type: N/A; Part Number: 18-28964; Part Type: IC\DIGITAL\OTHER; Revision: R003; RoHS Status: PART NOT KNOWN; Rtd Voltage: N/A; WEIGHT: N/A
Y1 = CRYSTAL: CRYSTAL, RESONATOR, 32.768kHz, -20PPM/+20PPM, -40DEGC/+85DEGC, SMD; ALT_SYMBOLS: XTAL_FC-135L,XTAL_FC-135M; AutoDoc File: http://notefied-dynamic-precision.com/DB/Apps/Desktop/Item/Object.aspx?id=91966; Budget Currency: USD; Budget Price: 1.25375; Capacitance: 7pF; Datasheet URL 1: http://www.eea.epson.com/portal/pls/portal/docs/1/1525528.PDF; Datasheet URL 2: http://www.eea.epson.com/portal/pls/portal/docs/1/1525451.PDF; Definied Quality: INDUSTRIAL; Esd Level: N/A; FPLIST: XTAL_FC-135N,XTAL_FC-135L,XTAL_FC-135M; Last Time Buy: N/A; Lead Time: 10; MPN: FC-135 32.7680KA-AG0; MPN Status: ACTIVE; MSL: N/A; MTBF: N/A; MTBF Standard: N/A; Manufacturer: EPSON; Max Oper Temp: +85DEGC; Max Tol: +20PPM; Min Oper Temp: -40DEGC; Min Tol: -20PPM; Mounting Type: SMD; NOTE Status: PREFERRED; Packing Size: 1000; Packing Type: TAPE_&_REEL; Part Number: 12-00546; Part Type: CRYSTAL\OSCILLATOR\MEMS; Revision: R001; RoHS Status: ROHS_COMPLIANT; WEIGHT: N/A
Y2 = XTAL_4PIN_S: CRYSTAL, CRYSTAL OSCILLATOR, 24MHz, -15PPM/DEGC/+15PPM/DEGC, -40DEGC/+85DEGC, SMD; ALT_SYMBOLS: OSCCC250X320X60-4L,OSCCC250X320X60-4M; AutoDoc File: http://notefied-dynamic-precision.com/DB/Apps/Desktop/Item/Object.aspx?id=96738; Budget Currency: EUR; Budget Price: 0.256; Capacitance: 9pF; Datasheet URL 1: http://www.eea.epson.com/portal/pls/portal/docs/1/1721495.PDF; Datasheet URL 2: http://www.epsondevice.com/docs/qd/en/DownloadServlet?id=ID000658; FPLIST: OSCCC250X320X60-4N,OSCCC250X320X60-4L,OSCCC250X320X60-4M; Lead Time: 12; MPN: TSX-3225 24.0000MF15X-AC3; MPN Status: ACTIVE; Manufacturer: EPSON; Max Oper Temp: +85DEGC; Max TC: +15PPM/DEGC; Max Tol: +10PPM; Min Oper Temp: -40DEGC; Min TC: -15PPM/DEGC; Min Tol: -10PPM; Mounting Type: SMD; NOTE Status: PREFERRED; Old Footprint: OSCCC250X320X60-4N; Packing Size: 250; Packing Type: TAPE_&_REEL; Part Number: 12-00757; Part Type: CRYSTAL\OSCILLATOR; Revision: R001; RoHS Status: ROHS_COMPLIANT

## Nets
GND: C1.2 C11.2 C12.2 C13.1 C14.1 C21.1 C41.2 C51.2 C131.2 C221.2 C231.2 C331.2 C341.2 C342.2 C343.2 C351.2 C441.2 C451.2 C461.2 C471.2 C481.2 C482.2 J1.2 J1.3 J1.4 J1.5 L15.2 P1.1 P1.19 P2.2 P2.20 U1.49(VSS) Y2.2 Y2.4
VDD_EB: FL1.2 P2.7 P2.9
VDDR: C331.1 C451.1 C481.1 C482.1 L331.2 U1.45(VDDR) U1.48(VDDR)
VDDS: C1.1 C131.1 C221.1 C341.1 C342.1 C343.1 C441.1 FL1.1 R351.2 U1.13(VDDS2) U1.22(VDDS3) U1.34(VDDS_DCDC) U1.44(VDDS)
DCDC_SW: L331.1 U1.33(DCDC_SW)
DIO_1: P1.5 U1.6(DIO_1)
DIO_2: P1.7 U1.7(DIO_2)
DIO_3: P1.9 U1.8(DIO_3)
DIO_4: P1.11 U1.9(DIO_4)
DIO_5: P1.13 U1.10(DIO_5)
DIO_6: P1.4 U1.11(DIO_6)
DIO_7: P1.2 U1.12(DIO_7)
DIO_8: P1.20 U1.14(DIO_8)
DIO_9: P1.18 U1.15(DIO_9)
DIO_10: P1.16 U1.16(DIO_10)
DIO_11: P1.14 U1.17(DIO_11)
DIO_12: P1.12 U1.18(DIO_12)
DIO_13: P1.15 U1.19(DIO_13)
DIO_14: P1.17 U1.20(DIO_14)
DIO_15: P1.6 U1.21(DIO_15)
DIO_16 / JTAG TDO: P2.19 U1.26(DIO_16)
DIO_17 / JTAG TDI: P2.17 U1.27(DIO_17)
DIO_18: P1.8 U1.28(DIO_18)
DIO_19: P1.10 U1.29(DIO_19)
DIO_20: P2.8 U1.30(DIO_20)
DIO_21: P2.18 U1.31(DIO_21)
DIO_22: P1.3 U1.32(DIO_22)
DIO_23: P2.5 U1.36(DIO_23)
DIO_24: P2.10 U1.37(DIO_24)
DIO_25: P2.11 U1.38(DIO_25)
DIO_26: P2.6 U1.39(DIO_26)
DIO_27: P2.13 U1.40(DIO_27)
DIO_28: P2.16 U1.41(DIO_28)
DIO_29: P2.14 U1.42(DIO_29)
DIO_30: P2.12 U1.43(DIO_30)
JTAG_TCK: P2.1 U1.25(JTAG_TCKC)
JTAG_TMS: P2.4 U1.24(JTAG_TMSC)
nRESET: C351.1 P2.15 R351.1 U1.35(RESET_N)
N485531: J1.1 R11.1
N485535: A1.1(FEED/GND) L15.1 R13.1
N485571: C461.1 U1.46(X24M_N) Y2.3
N485643: C22.1 L11.2 L21.1 U1.2(RF_N)
N485645: C11.1 L11.1 L12.1 U1.1(RF_P)
N485661: C12.1 C22.2 L12.2 L13.1
N485675: C13.2 L13.2 L14.1
N485699: C231.1 U1.23(DCOUPL)
N485701: C41.1 U1.4(X32K_Q1) Y1.1
N485707: C51.1 U1.5(X32K_Q2) Y1.2
N485827: C14.2 C15.2 L14.2
N485893: C15.1 R11.2 R12.1
N485901: R12.2 R13.2
N485927: C21.2 L21.2 U1.3(RX_TX)
N485953: C471.1 U1.47(X24M_P) Y2.1

Not connected (* = marked no-connect by the designer): FIDU1 1*; FIDU2 1*; FIDU3 1*; FIDU4 1*; FIDU5 1*; FIDU6 1*; P2 3*

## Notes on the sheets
sheet 1
- VDDS decoupling capacitors
- VDDR decoupling capacitors
- VDDS Decoupling Capacitors
- VDDR Decoupling Capacitors
- Pin 13
- Pin 22
- Pin 44
- Pin 34
- Pin 45
- Pin 48
- Place L331 and C331 close to pin 33.
  Low inductance ground for C331
- Mount either R11 or R12
  To select SMA or PCB ant.
- EM connector 1
- EM connector 2
sheet 2
- R 1.0.0
  --------------------------------------------------------------------------------------------
  -Initial release revision. Based on CC13xxEM-7XD-7793 R1.3.3
  R1.0.1
  ---------------------------------------------------------------------------------------------
  - L11 -> 27nH
  - C14 -> 3.0pF
